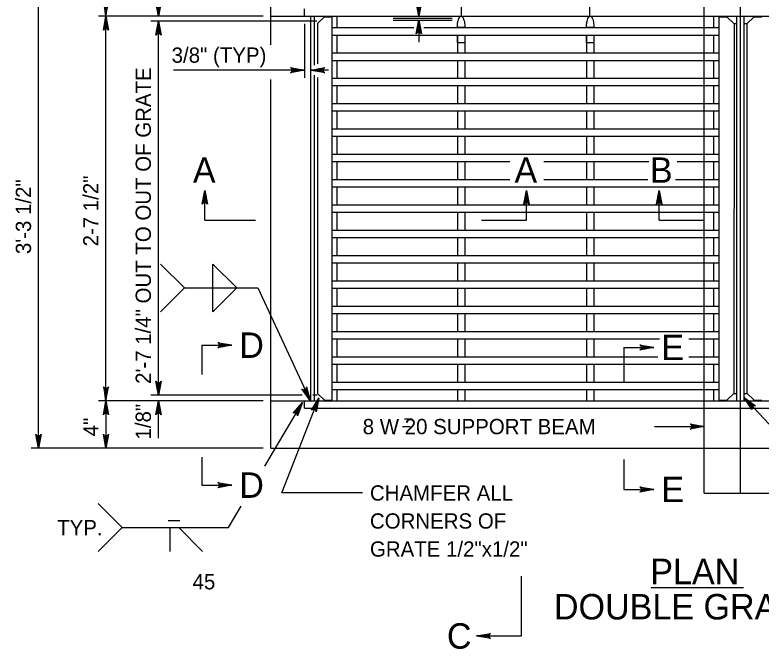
# Model space of a CAD drawing. Extents: x 0.7 to 7.67, y -7.49 to 2.47.
# Drawn here: x 1.023 to 3.951, y -1.379 to 1.111 of the extents above; entities that cross this region are included whole.
import ezdxf

# ---------------------------------------------------------------- set-up
doc = ezdxf.new("R2010")
doc.units = 0
for name, color, linetype in [('DETL-DIMS', 7, 'Continuous'), ('DETL-LINE', 7, 'Continuous'), ('DETL-NOTE', 7, 'Continuous'), ('DETL-TITL', 7, 'Continuous')]:
    doc.layers.add(name, color=color, linetype=linetype)

msp = doc.modelspace()

# ---------------------------------------------------------------- linework, layer by layer
at = {"layer": 'DETL-DIMS'}
for p, q in [((3.2796, 1.106), (3.2796, 1.9099)), ((2.7751, 1.106), (2.7751, 1.4641)), ((3.8693, 1.3894), (3.8693, -0.7657)), ((1.1152, -0.5901), (1.1152, 1.2922)), ((1.3799, 1.106), (1.3799, 1.2922)), ((1.5858, 1.106), (1.5858, 1.253)), ((2.608, 1.2422), (2.608, 1.106)), ((1.9975, 1.106), (1.3505, 1.106)), ((1.3799, -0.4038), (1.3799, 1.106)), ((2.2079, 1.0862), (1.5563, 1.0862)), ((1.5858, -0.3814), (1.5858, 1.0862)), ((2.608, 1.0914), (2.608, 1.0038)), ((2.1593, 1.0766), (2.1593, 0.8647)), ((2.1593, 0.8941), (1.6449, 0.8941)), ((2.2535, 0.8941), (2.1838, 0.8941)), ((1.7681, 0.3053), (1.7681, 0.4225)), ((3.0302, 0.3053), (3.0302, 0.4225)), ((3.5514, 0.3053), (3.5514, 0.4225)), ((1.7681, 0.3053), (1.9666, 0.3053)), ((2.8537, 0.3053), (3.0302, 0.3053)), ((3.5514, 0.3053), (3.7279, 0.3053)), ((1.9763, 0.0391), (2.1809, -0.4027)), ((1.756, -0.1854), (1.8736, -0.1854)), ((1.756, -0.1854), (1.756, -0.3012)), ((3.4126, -0.1943), (3.5302, -0.1943)), ((3.4126, -0.1943), (3.4126, -0.3303)), ((1.9975, -0.4038), (1.3505, -0.4038)), ((1.3799, -0.4038), (1.3799, -0.5901)), ((2.1494, -0.3814), (1.5563, -0.3814)), ((1.5858, -0.5509), (1.5858, -0.4038)), ((2.0701, -0.7658), (2.2159, -0.393)), ((2.2091, -0.3814), (2.1916, -0.3814)), ((4.262, -0.7972), (3.8847, -0.3909)), ((2.003, -0.6611), (2.1509, -0.4103)), ((3.5328, -0.5051), (3.7238, -0.5051)), ((1.9975, -0.5901), (1.0858, -0.5901)), ((1.756, -0.6258), (1.756, -0.7349)), ((3.4126, -0.6342), (3.4126, -0.7519)), ((1.756, -0.7349), (1.8736, -0.7349)), ((3.4126, -0.7519), (3.5302, -0.7519)), ((2.3866, -0.7658), (2.0701, -0.7658)), ((1.8609, -0.9019), (1.9104, -0.8179)), ((1.6239, -0.8742), (1.6697, -0.8742)), ((1.4436, -0.9019), (1.726, -0.9019)), ((1.6318, -0.996), (1.6318, -0.9019)), ((1.6653, -0.9019), (1.7594, -0.996)), ((1.726, -0.9019), (1.8609, -0.9019)), ((3.0104, -1.3274), (3.0104, -1.0921)), ((2.834, -1.3274), (3.0104, -1.3274))]:
    msp.add_line(p, q, dxfattribs=at)
for points in [[(1.3799, 1.106), (1.3902, 1.1608), (1.3872, 1.1566), (1.3835, 1.1544), (1.3799, 1.1538), (1.3762, 1.1544), (1.3725, 1.1566), (1.3696, 1.1608), (1.3799, 1.106), (1.3725, 1.1566), (1.3762, 1.1544), (1.3799, 1.106), (1.3799, 1.1538), (1.3835, 1.1544), (1.3799, 1.106), (1.3872, 1.1566)], [(1.5858, 1.106), (1.5755, 1.1608), (1.5784, 1.1566), (1.5821, 1.1544), (1.5858, 1.1538), (1.5894, 1.1544), (1.5931, 1.1566), (1.596, 1.1608), (1.5858, 1.106), (1.5931, 1.1566), (1.5894, 1.1544), (1.5858, 1.106), (1.5858, 1.1538), (1.5821, 1.1544), (1.5858, 1.106), (1.5784, 1.1566)], [(2.608, 1.106), (2.5977, 1.1608), (2.6007, 1.1566), (2.6043, 1.1544), (2.608, 1.1538), (2.6117, 1.1544), (2.6154, 1.1566), (2.6183, 1.1608), (2.608, 1.106), (2.6154, 1.1566), (2.6117, 1.1544), (2.608, 1.106), (2.608, 1.1538), (2.6043, 1.1544), (2.608, 1.106), (2.6007, 1.1566)], [(1.3799, 1.106), (1.3902, 1.0511), (1.3872, 1.0554), (1.3835, 1.0575), (1.3799, 1.0582), (1.3762, 1.0575), (1.3725, 1.0554), (1.3696, 1.0511), (1.3799, 1.106), (1.3725, 1.0554), (1.3762, 1.0575), (1.3799, 1.106), (1.3799, 1.0582), (1.3835, 1.0575), (1.3799, 1.106), (1.3872, 1.0554)], [(1.5858, 1.0862), (1.596, 1.0314), (1.5931, 1.0356), (1.5894, 1.0378), (1.5858, 1.0384), (1.5821, 1.0378), (1.5784, 1.0356), (1.5755, 1.0314), (1.5858, 1.0862), (1.5784, 1.0356), (1.5821, 1.0378), (1.5858, 1.0862), (1.5858, 1.0384), (1.5894, 1.0378), (1.5858, 1.0862), (1.5931, 1.0356)], [(2.608, 1.0914), (2.6183, 1.0365), (2.6154, 1.0408), (2.6117, 1.0429), (2.608, 1.0436), (2.6043, 1.0429), (2.6007, 1.0408), (2.5977, 1.0365), (2.608, 1.0914), (2.6007, 1.0408), (2.6043, 1.0429), (2.608, 1.0914), (2.608, 1.0436), (2.6117, 1.0429), (2.608, 1.0914), (2.6154, 1.0408)], [(2.1593, 0.8941), (2.1045, 0.8838), (2.1087, 0.8867), (2.1109, 0.8904), (2.1115, 0.8941), (2.1109, 0.8978), (2.1087, 0.9014), (2.1045, 0.9044), (2.1593, 0.8941), (2.1087, 0.9014), (2.1109, 0.8978), (2.1593, 0.8941), (2.1115, 0.8941), (2.1109, 0.8904), (2.1593, 0.8941), (2.1087, 0.8867)], [(2.1838, 0.8941), (2.2386, 0.9044), (2.2344, 0.9014), (2.2322, 0.8978), (2.2316, 0.8941), (2.2322, 0.8904), (2.2344, 0.8867), (2.2386, 0.8838), (2.1838, 0.8941), (2.2344, 0.8867), (2.2322, 0.8904), (2.1838, 0.8941), (2.2316, 0.8941), (2.2322, 0.8978), (2.1838, 0.8941), (2.2344, 0.9014)], [(1.7681, 0.4225), (1.7784, 0.3677), (1.7755, 0.3719), (1.7718, 0.3741), (1.7681, 0.3747), (1.7644, 0.3741), (1.7608, 0.3719), (1.7578, 0.3677), (1.7681, 0.4225), (1.7608, 0.3719), (1.7644, 0.3741), (1.7681, 0.4225), (1.7681, 0.3747), (1.7718, 0.3741), (1.7681, 0.4225), (1.7755, 0.3719)], [(3.0302, 0.4225), (3.0405, 0.3677), (3.0376, 0.3719), (3.0339, 0.3741), (3.0302, 0.3747), (3.0265, 0.3741), (3.0228, 0.3719), (3.0199, 0.3677), (3.0302, 0.4225), (3.0228, 0.3719), (3.0265, 0.3741), (3.0302, 0.4225), (3.0302, 0.3747), (3.0339, 0.3741), (3.0302, 0.4225), (3.0376, 0.3719)], [(3.5514, 0.4225), (3.5617, 0.3677), (3.5588, 0.3719), (3.5551, 0.3741), (3.5514, 0.3747), (3.5478, 0.3741), (3.5441, 0.3719), (3.5412, 0.3677), (3.5514, 0.4225), (3.5441, 0.3719), (3.5478, 0.3741), (3.5514, 0.4225), (3.5514, 0.3747), (3.5551, 0.3741), (3.5514, 0.4225), (3.5588, 0.3719)], [(1.5945, 0.1332), (1.6887, 0.0391), (1.5945, -0.055)], [(1.6887, 0.0391), (1.893, 0.0391), (1.7988, -0.055), (1.7988, 0.1332), (1.893, 0.0391), (1.9763, 0.0391)], [(1.8736, -0.1854), (1.8188, -0.1957), (1.823, -0.1928), (1.8252, -0.1891), (1.8259, -0.1854), (1.8252, -0.1817), (1.823, -0.1781), (1.8188, -0.1751), (1.8736, -0.1854), (1.823, -0.1781), (1.8252, -0.1817), (1.8736, -0.1854), (1.8259, -0.1854), (1.8252, -0.1891), (1.8736, -0.1854), (1.823, -0.1928)], [(3.5302, -0.1943), (3.4754, -0.2045), (3.4796, -0.2016), (3.4818, -0.1979), (3.4824, -0.1943), (3.4818, -0.1906), (3.4796, -0.1869), (3.4754, -0.184), (3.5302, -0.1943), (3.4796, -0.1869), (3.4818, -0.1906), (3.5302, -0.1943), (3.4824, -0.1943), (3.4818, -0.1979), (3.5302, -0.1943), (3.4796, -0.2016)], [(1.3799, -0.4038), (1.3902, -0.349), (1.3872, -0.3532), (1.3835, -0.3554), (1.3799, -0.356), (1.3762, -0.3554), (1.3725, -0.3532), (1.3696, -0.349), (1.3799, -0.4038), (1.3725, -0.3532), (1.3762, -0.3554), (1.3799, -0.4038), (1.3799, -0.356), (1.3835, -0.3554), (1.3799, -0.4038), (1.3872, -0.3532)], [(1.5858, -0.3814), (1.5755, -0.3266), (1.5784, -0.3308), (1.5821, -0.333), (1.5858, -0.3337), (1.5894, -0.333), (1.5931, -0.3308), (1.596, -0.3266), (1.5858, -0.3814), (1.5931, -0.3308), (1.5894, -0.333), (1.5858, -0.3814), (1.5858, -0.3337), (1.5821, -0.333), (1.5858, -0.3814), (1.5784, -0.3308)], [(2.1809, -0.4027), (2.1485, -0.3572), (2.153, -0.3598), (2.1572, -0.3603), (2.1608, -0.3593), (2.1639, -0.3572), (2.1663, -0.3537), (2.1672, -0.3486), (2.1809, -0.4027), (2.1663, -0.3537), (2.1639, -0.3572), (2.1809, -0.4027), (2.1608, -0.3593), (2.1572, -0.3603), (2.1809, -0.4027), (2.153, -0.3598)], [(1.3799, -0.4038), (1.3902, -0.4587), (1.3872, -0.4544), (1.3835, -0.4523), (1.3799, -0.4516), (1.3762, -0.4523), (1.3725, -0.4544), (1.3696, -0.4587), (1.3799, -0.4038), (1.3725, -0.4544), (1.3762, -0.4523), (1.3799, -0.4038), (1.3799, -0.4516), (1.3835, -0.4523), (1.3799, -0.4038), (1.3872, -0.4544)], [(1.5858, -0.4038), (1.596, -0.4587), (1.5931, -0.4544), (1.5894, -0.4523), (1.5858, -0.4516), (1.5821, -0.4523), (1.5784, -0.4544), (1.5755, -0.4587), (1.5858, -0.4038), (1.5784, -0.4544), (1.5821, -0.4523), (1.5858, -0.4038), (1.5858, -0.4516), (1.5894, -0.4523), (1.5858, -0.4038), (1.5931, -0.4544)], [(2.2159, -0.393), (2.2055, -0.4478), (2.2043, -0.4428), (2.2016, -0.4394), (2.1985, -0.4375), (2.1948, -0.4368), (2.1906, -0.4374), (2.1863, -0.4403), (2.2159, -0.393), (2.1906, -0.4374), (2.1948, -0.4368), (2.2159, -0.393), (2.1985, -0.4375), (2.2016, -0.4394), (2.2159, -0.393), (2.2043, -0.4428)], [(3.8847, -0.3909), (3.9296, -0.4241), (3.9245, -0.423), (3.9204, -0.4239), (3.9172, -0.426), (3.915, -0.4289), (3.9138, -0.433), (3.9145, -0.4381), (3.8847, -0.3909), (3.9138, -0.433), (3.915, -0.4289), (3.8847, -0.3909), (3.9172, -0.426), (3.9204, -0.4239), (3.8847, -0.3909), (3.9245, -0.423)], [(2.1509, -0.4103), (2.1319, -0.4627), (2.1315, -0.4576), (2.1295, -0.4538), (2.1266, -0.4514), (2.1231, -0.4501), (2.1189, -0.4501), (2.1142, -0.4523), (2.1509, -0.4103), (2.1189, -0.4501), (2.1231, -0.4501), (2.1509, -0.4103), (2.1266, -0.4514), (2.1295, -0.4538), (2.1509, -0.4103), (2.1315, -0.4576)], [(3.7279, -0.5051), (3.6731, -0.5154), (3.6773, -0.5125), (3.6795, -0.5088), (3.6801, -0.5051), (3.6795, -0.5014), (3.6773, -0.4978), (3.6731, -0.4948), (3.7279, -0.5051), (3.6773, -0.4978), (3.6795, -0.5014), (3.7279, -0.5051), (3.6801, -0.5051), (3.6795, -0.5088), (3.7279, -0.5051), (3.6773, -0.5125)], [(1.1152, -0.5901), (1.1049, -0.5353), (1.1078, -0.5395), (1.1115, -0.5417), (1.1152, -0.5423), (1.1188, -0.5417), (1.1225, -0.5395), (1.1254, -0.5353), (1.1152, -0.5901), (1.1225, -0.5395), (1.1188, -0.5417), (1.1152, -0.5901), (1.1152, -0.5423), (1.1115, -0.5417), (1.1152, -0.5901), (1.1078, -0.5395)], [(1.3799, -0.5901), (1.3696, -0.5353), (1.3725, -0.5395), (1.3762, -0.5417), (1.3799, -0.5423), (1.3835, -0.5417), (1.3872, -0.5395), (1.3902, -0.5353), (1.3799, -0.5901), (1.3872, -0.5395), (1.3835, -0.5417), (1.3799, -0.5901), (1.3799, -0.5423), (1.3762, -0.5417), (1.3799, -0.5901), (1.3725, -0.5395)], [(1.8736, -0.7349), (1.8188, -0.7451), (1.823, -0.7422), (1.8252, -0.7385), (1.8259, -0.7349), (1.8252, -0.7312), (1.823, -0.7275), (1.8188, -0.7246), (1.8736, -0.7349), (1.823, -0.7275), (1.8252, -0.7312), (1.8736, -0.7349), (1.8259, -0.7349), (1.8252, -0.7385), (1.8736, -0.7349), (1.823, -0.7422)], [(3.5302, -0.7519), (3.4754, -0.7622), (3.4796, -0.7592), (3.4818, -0.7556), (3.4824, -0.7519), (3.4818, -0.7482), (3.4796, -0.7445), (3.4754, -0.7416), (3.5302, -0.7519), (3.4796, -0.7445), (3.4818, -0.7482), (3.5302, -0.7519), (3.4824, -0.7519), (3.4818, -0.7556), (3.5302, -0.7519), (3.4796, -0.7592)], [(1.3495, -0.8077), (1.4436, -0.9019), (1.3495, -0.996)], [(2.834, -1.3274), (2.8888, -1.3171), (2.8846, -1.32), (2.8824, -1.3237), (2.8818, -1.3274), (2.8824, -1.3311), (2.8846, -1.3347), (2.8888, -1.3377), (2.834, -1.3274), (2.8846, -1.3347), (2.8824, -1.3311), (2.834, -1.3274), (2.8818, -1.3274), (2.8824, -1.3237), (2.834, -1.3274), (2.8846, -1.32)]]:
    msp.add_lwpolyline(points, dxfattribs=at)
at = {"layer": 'DETL-LINE'}
for p, q in [((3.7279, -0.7666), (3.7279, 1.5275)), ((2.0269, 0.9942), (2.0269, 1.2922)), ((2.1593, 1.106), (2.1593, 1.1354)), ((2.0269, 1.106), (5.7132, 1.106)), ((2.1838, -0.4038), (2.1838, 1.106)), ((2.1985, 0.9139), (2.1985, 1.106)), ((2.2112, 1.0792), (2.2377, 1.1034)), ((2.2377, 1.1034), (2.2671, 1.1034)), ((2.2671, -0.4038), (2.2671, 1.106)), ((2.2877, 1.0619), (2.2877, 1.106)), ((2.5069, 1.0982), (2.7388, 1.0982)), ((2.5069, 1.0913), (2.7388, 1.0913)), ((3.7661, 1.0619), (3.7661, 1.106)), ((3.7867, -0.4038), (3.7867, 1.106)), ((3.7867, 1.1033), (3.8161, 1.1033)), ((3.8456, 1.0766), (3.8161, 1.1033)), ((3.8554, -0.4038), (3.8554, 1.106)), ((3.8848, -0.4038), (3.8848, 1.106)), ((3.8946, 1.0766), (3.924, 1.1034)), ((3.924, 1.1034), (3.9534, 1.1034)), ((2.2112, 0.9195), (2.2112, 1.0792)), ((2.2671, 1.0619), (2.5878, 1.0619)), ((2.6272, 1.0619), (3.7867, 1.0619)), ((3.8456, 1.0766), (3.8447, -0.3752)), ((3.8566, 1.0766), (3.8456, 1.0766)), ((3.8946, 1.0766), (3.886, 1.0766)), ((3.8946, 1.0766), (3.8951, -0.3749)), ((2.2671, 1.0324), (3.7867, 1.0324)), ((2.2877, 0.9624), (2.2877, 1.0324)), ((2.759, 1.0324), (2.759, 0.9624)), ((2.7884, 1.0324), (2.7884, 0.9624)), ((3.2655, 1.0324), (3.2655, 0.9624)), ((3.2949, 1.0324), (3.2949, 0.9624)), ((3.7661, 0.9624), (3.7661, 1.0324)), ((2.2671, 0.9624), (3.7867, 0.9624)), ((2.2671, 0.933), (3.7867, 0.933)), ((2.2877, 0.863), (2.2877, 0.933)), ((2.759, 0.933), (2.759, 0.863)), ((2.7884, 0.933), (2.7884, 0.863)), ((3.2655, 0.933), (3.2655, 0.863)), ((3.2949, 0.933), (3.2949, 0.863)), ((3.7661, 0.863), (3.7661, 0.933)), ((2.0269, -0.5901), (2.0269, 0.8581)), ((2.1985, -0.4038), (2.1985, 0.8745)), ((2.2112, -0.3771), (2.2112, 0.8661)), ((2.2671, 0.863), (3.7867, 0.863)), ((2.2671, 0.8336), (3.7867, 0.8336)), ((2.2877, 0.7635), (2.2877, 0.8336)), ((2.759, 0.8336), (2.759, 0.7635)), ((2.7884, 0.8336), (2.7884, 0.7635)), ((3.2655, 0.8336), (3.2655, 0.7635)), ((3.2949, 0.8336), (3.2949, 0.7635)), ((3.7661, 0.7635), (3.7661, 0.8336)), ((2.2671, 0.7635), (3.7867, 0.7635)), ((2.2671, 0.7341), (3.7867, 0.7341)), ((2.2877, 0.6641), (2.2877, 0.7341)), ((2.759, 0.7341), (2.759, 0.6641)), ((2.7884, 0.7341), (2.7884, 0.6641)), ((3.2655, 0.7341), (3.2655, 0.6641)), ((3.2949, 0.7341), (3.2949, 0.6641)), ((3.7661, 0.6641), (3.7661, 0.7341)), ((2.2671, 0.6641), (3.7867, 0.6641)), ((2.2671, 0.6347), (3.7867, 0.6347)), ((2.2877, 0.5646), (2.2877, 0.6347)), ((2.759, 0.6347), (2.759, 0.5646)), ((2.7884, 0.6347), (2.7884, 0.5646)), ((3.2655, 0.6347), (3.2655, 0.5646)), ((3.2949, 0.6347), (3.2949, 0.5646)), ((3.7661, 0.5646), (3.7661, 0.6347)), ((2.2671, 0.5646), (3.7867, 0.5646)), ((2.2671, 0.5352), (2.9646, 0.5352)), ((2.2877, 0.4652), (2.2877, 0.5352)), ((2.759, 0.5352), (2.759, 0.4652)), ((2.7884, 0.5352), (2.7884, 0.4652)), ((3.0985, 0.5352), (3.5102, 0.5352)), ((3.2655, 0.5352), (3.2655, 0.4652)), ((3.2949, 0.5352), (3.2949, 0.4652)), ((3.6213, 0.5352), (3.7867, 0.5352)), ((3.7661, 0.4652), (3.7661, 0.5352)), ((2.2671, 0.4652), (2.9646, 0.4652)), ((3.0985, 0.4652), (3.507, 0.4652)), ((3.6148, 0.4652), (3.7867, 0.4652)), ((2.2671, 0.4358), (3.7867, 0.4358)), ((2.2877, 0.3658), (2.2877, 0.4358)), ((2.759, 0.4358), (2.759, 0.3658)), ((2.7884, 0.4358), (2.7884, 0.3658)), ((3.2655, 0.4358), (3.2655, 0.3658)), ((3.2949, 0.4358), (3.2949, 0.3658)), ((3.7661, 0.3658), (3.7661, 0.4358)), ((2.2671, 0.3658), (3.7867, 0.3658)), ((2.2671, 0.3364), (3.7867, 0.3364)), ((2.2877, 0.2663), (2.2877, 0.3364)), ((2.759, 0.3364), (2.759, 0.2663)), ((2.7884, 0.3364), (2.7884, 0.2663)), ((3.2655, 0.3364), (3.2655, 0.2663)), ((3.2949, 0.3364), (3.2949, 0.2663)), ((3.7661, 0.2663), (3.7661, 0.3364)), ((2.2671, 0.2663), (3.7867, 0.2663)), ((2.2671, 0.2369), (3.7867, 0.2369)), ((2.2877, 0.1669), (2.2877, 0.2369)), ((2.759, 0.2369), (2.759, 0.1669)), ((2.7884, 0.2369), (2.7884, 0.1669)), ((3.2655, 0.2369), (3.2655, 0.1669)), ((3.2949, 0.2369), (3.2949, 0.1669)), ((3.7661, 0.1669), (3.7661, 0.2369)), ((2.2671, 0.1669), (3.7867, 0.1669)), ((2.2671, 0.1375), (3.7867, 0.1375)), ((2.2877, 0.0674), (2.2877, 0.1375)), ((2.759, 0.1375), (2.759, 0.0674)), ((2.7884, 0.1375), (2.7884, 0.0674)), ((3.2655, 0.1375), (3.2655, 0.0674)), ((3.2949, 0.1375), (3.2949, 0.0674)), ((3.7661, 0.0674), (3.7661, 0.1375)), ((2.2671, 0.0674), (3.7867, 0.0674)), ((2.2671, 0.038), (3.7867, 0.038)), ((2.2877, -0.032), (2.2877, 0.038)), ((2.759, 0.038), (2.759, -0.032)), ((2.7884, 0.038), (2.7884, -0.032)), ((3.2655, 0.038), (3.2655, -0.032)), ((3.2949, 0.038), (3.2949, -0.032)), ((3.7661, -0.032), (3.7661, 0.038)), ((2.2671, -0.032), (3.7867, -0.032)), ((2.2671, -0.0614), (3.7867, -0.0614)), ((2.2877, -0.1314), (2.2877, -0.0614)), ((2.759, -0.0614), (2.759, -0.1314)), ((2.7884, -0.0614), (2.7884, -0.1314)), ((3.2655, -0.0614), (3.2655, -0.1314)), ((3.2949, -0.0614), (3.2949, -0.1314)), ((3.7661, -0.1314), (3.7661, -0.0614)), ((2.2671, -0.1314), (3.7867, -0.1314)), ((2.2671, -0.1609), (3.5527, -0.1609)), ((2.2877, -0.2309), (2.2877, -0.1609)), ((2.759, -0.1609), (2.759, -0.2309)), ((2.7884, -0.1609), (2.7884, -0.2309)), ((3.2655, -0.1609), (3.2655, -0.2309)), ((3.2949, -0.1609), (3.2949, -0.2309)), ((3.6671, -0.1609), (3.7867, -0.1609)), ((3.7661, -0.2309), (3.7661, -0.1609)), ((2.2671, -0.2309), (3.5462, -0.2309)), ((3.6671, -0.2309), (3.7867, -0.2309)), ((2.2671, -0.2603), (3.7867, -0.2603)), ((2.2877, -0.3303), (2.2877, -0.2603)), ((2.759, -0.2603), (2.759, -0.3303)), ((2.7884, -0.2603), (2.7884, -0.3303)), ((3.2655, -0.2603), (3.2655, -0.3303)), ((3.2949, -0.2603), (3.2949, -0.3303)), ((3.7661, -0.3303), (3.7661, -0.2603)), ((2.2671, -0.3303), (3.7867, -0.3303)), ((2.2112, -0.3771), (2.2377, -0.401)), ((2.2671, -0.3597), (3.7867, -0.3597)), ((2.2877, -0.4038), (2.2877, -0.3597)), ((2.759, -0.3597), (2.759, -0.4038)), ((2.7884, -0.3597), (2.7884, -0.4038)), ((3.2655, -0.3597), (3.2655, -0.4038)), ((3.2949, -0.3597), (3.2949, -0.4038)), ((3.7661, -0.4038), (3.7661, -0.3597)), ((3.8456, -0.3744), (3.8161, -0.4012)), ((3.8447, -0.3752), (3.8533, -0.3751)), ((3.8844, -0.3749), (3.8951, -0.3749)), ((3.8946, -0.3744), (3.924, -0.401)), ((2.0269, -0.4038), (5.7132, -0.4038)), ((2.1593, -0.4332), (2.1593, -0.4038)), ((2.2377, -0.401), (2.2671, -0.401)), ((3.7867, -0.4012), (3.8161, -0.4012)), ((3.924, -0.401), (3.9534, -0.401)), ((2.1593, -0.4332), (5.5809, -0.4332)), ((2.0269, -0.5901), (5.7132, -0.5901)), ((3.7279, -0.7666), (4.0122, -0.7666))]:
    msp.add_line(p, q, dxfattribs=at)
for points in [[(2.759, 1.0619), (2.7592, 1.0705), (2.7597, 1.0752), (2.7601, 1.0788), (2.7606, 1.0827), (2.7615, 1.0874), (2.7629, 1.0925), (2.7648, 1.0972), (2.7672, 1.1018), (2.7693, 1.1042), (2.7715, 1.1058), (2.7737, 1.106), (2.7754, 1.106), (2.7767, 1.1052), (2.7783, 1.1038), (2.7796, 1.1022), (2.7813, 1.0995), (2.7836, 1.0945), (2.7855, 1.0883), (2.7866, 1.0825), (2.7874, 1.0774), (2.7879, 1.0729), (2.7883, 1.0686), (2.7884, 1.0619)], [(3.2655, 1.0619), (3.2658, 1.0705), (3.2662, 1.0752), (3.2667, 1.0788), (3.2671, 1.0827), (3.2681, 1.0874), (3.2694, 1.0925), (3.2713, 1.0972), (3.2737, 1.1018), (3.2758, 1.1042), (3.278, 1.1058), (3.2803, 1.106), (3.2819, 1.106), (3.2832, 1.1052), (3.2848, 1.1038), (3.2862, 1.1022), (3.2878, 1.0995), (3.2901, 1.0945), (3.2921, 1.0883), (3.2931, 1.0825), (3.2939, 1.0774), (3.2945, 1.0729), (3.2948, 1.0686), (3.2949, 1.0619)], [(2.759, 1.0324), (2.788, 1.0324), (2.788, 1.0014), (2.759, 1.0014)], [(3.2655, 1.0324), (3.2946, 1.0324), (3.2946, 1.0014), (3.2655, 1.0014)]]:
    msp.add_lwpolyline(points, close=True, dxfattribs=at)
at = {"layer": 'DETL-NOTE'}
for p, q in [((2.5519, -0.4748), (2.5818, -0.4748)), ((2.5442, -0.5042), (2.5741, -0.5042))]:
    msp.add_line(p, q, dxfattribs=at)
at = {"layer": 'DETL-TITL'}
msp.add_line((3.52, -1.1366), (3.8819, -1.1366), dxfattribs=at)

# ---------------------------------------------------------------- texts
at = {"layer": 'DETL-NOTE'}
for s, p in [('3/8" (TYP)', (1.6377, 0.9235)), ('8 W 20 SUPPORT BEAM', (2.3876, -0.5351)), ('CHAMFER ALL', (2.416, -0.7958)), ('CORNERS OF', (2.416, -0.9058)), ('TYP.', (1.1883, -0.9319)), ('GRATE 1/2"x1/2"', (2.416, -1.0158)), ('45', (1.7198, -1.1443))]:
    msp.add_text(s, height=0.06, dxfattribs=at).set_placement(p)
for s, p in [('2\'-7 1/4" OUT TO OUT OF GRATE', (1.5563, -0.3375)), ('2-7 1/2"', (1.3505, 0.2023)), ('3\'-3 1/2"', (1.0858, 0.1723)), ('1/8"', (1.5563, -0.5559)), ('4"', (1.3505, -0.5433))]:
    msp.add_text(s, height=0.06, rotation=90, dxfattribs=at).set_placement(p)
at = {"layer": 'DETL-TITL'}
for s, p in [('A', (1.7211, 0.452)), ('A', (2.9832, 0.452)), ('B', (3.5147, 0.452)), ('D', (1.9031, -0.2354)), ('E', (3.5596, -0.2443)), ('D', (1.9031, -0.7849)), ('E', (3.5596, -0.8019)), ('PLAN', (3.5163, -1.124)), ('DOUBLE GRATE', (3.1381, -1.2624)), ('C', (2.718, -1.3774))]:
    msp.add_text(s, height=0.1, dxfattribs=at).set_placement(p)

doc.saveas('drawing.dxf')
